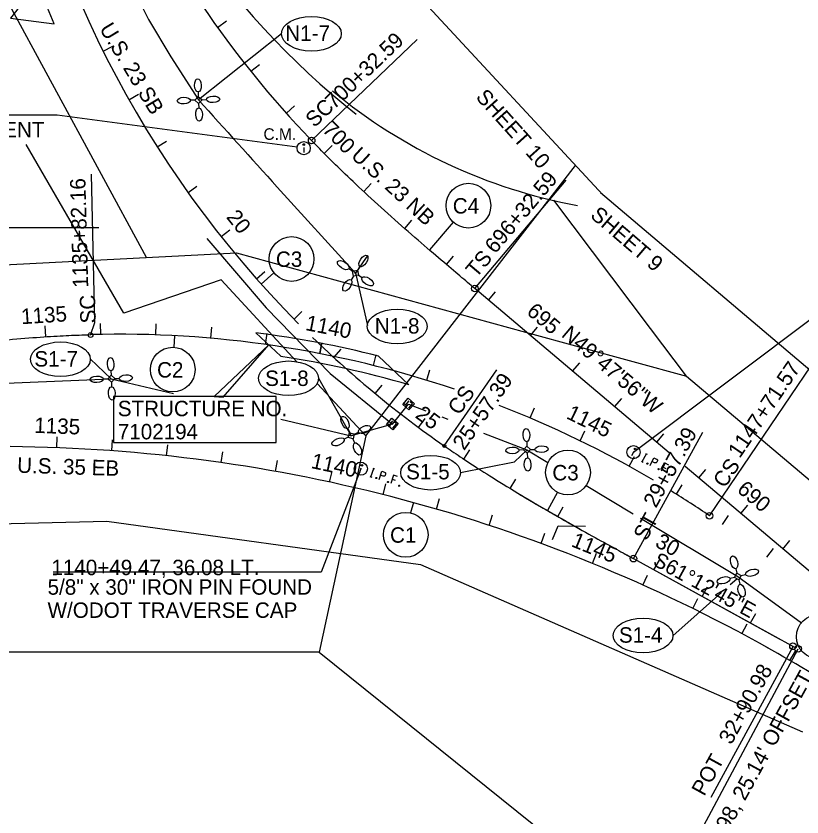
# Model space of a CAD drawing. Extents: x 310 to 1844719, y 48 to 494239.
# Drawn here: x 1837039 to 1838467, y 491132 to 492586 of the extents above; entities that cross this region are included whole.
import ezdxf

# ---------------------------------------------------------------- set-up
doc = ezdxf.new("R2010")
doc.units = 0
for name, color, linetype in [('BR_X_SV_Bottom_of_Beam_Text', 7, 'Continuous'), ('Default', 7, 'Continuous'), ('Guardrail', 7, 'Continuous'), ('LT_P_Control_Center', 7, 'Continuous'), ('LT_P_PullBox', 7, 'Continuous'), ('PV_X_Curb', 7, 'Continuous'), ('PV_X_EOP', 7, 'Continuous'), ('RW_X_CL_100_Stations', 7, 'Continuous'), ('RW_X_Esmt_LA', 7, 'Continuous'), ('SC_Scratch2', 7, 'Continuous'), ('Shoulder lines', 7, 'Continuous'), ('Traffic Sign', 7, 'Continuous'), ('UT_P_Electric_Cells', 7, 'Continuous'), ('VG_X_Tree_Line_Lt', 7, 'Continuous'), ('VG_X_Tree_Line_Rt', 7, 'Continuous')]:
    doc.layers.add(name, color=color, linetype=linetype)

msp = doc.modelspace()

# ---------------------------------------------------------------- linework, layer by layer
at = {"layer": 'BR_X_SV_Bottom_of_Beam_Text'}
for p, q in [((1837561.9, 492347.3), (1837561.9, 492338.5)), ((1838161.3, 491795.4), (1838157.3, 491787.5)), ((1837665.9, 491765.5), (1837663.1, 491757.1))]:
    msp.add_line(p, q, dxfattribs=at)
for points in [[(1838176.8, 491777.3), (1838184.1, 491791.5)], [(1838182.5, 491792.3), (1838185.7, 491790.7)], [(1838175.3, 491778), (1838178.4, 491776.5)], [(1838186.4, 491774.8), (1838186.9, 491774.6), (1838187, 491774.2), (1838187.1, 491773.6), (1838186.8, 491773), (1838186.3, 491772.7), (1838185.9, 491772.7), (1838185.4, 491772.9), (1838185.2, 491773.3), (1838185.2, 491773.9), (1838185.4, 491774.4), (1838186, 491774.7), (1838186.4, 491774.8)], [(1838190.8, 491770.2), (1838198, 491784.4), (1838202.8, 491782), (1838203.2, 491781.7), (1838203.8, 491781.1), (1838204, 491780.7), (1838204.1, 491780.4), (1838204.2, 491779.6), (1838204.3, 491778.9), (1838204, 491777.9), (1838203.3, 491776.5), (1838203, 491776.1), (1838202.4, 491775.6), (1838201.7, 491775), (1838201.1, 491774.8), (1838200.7, 491774.8), (1838200.1, 491774.8), (1838199.2, 491775.1), (1838194.5, 491777.5)], [(1837683.9, 491749.7), (1837689, 491764.9)], [(1837687.3, 491765.4), (1837690.7, 491764.3)], [(1838206.4, 491764.7), (1838206.9, 491764.4), (1838207.1, 491764), (1838207.2, 491763.4), (1838206.9, 491762.9), (1838206.4, 491762.6), (1838205.9, 491762.5), (1838205.5, 491762.7), (1838205.3, 491763.1), (1838205.2, 491763.7), (1838205.5, 491764.3), (1838206, 491764.6), (1838206.4, 491764.7)], [(1838224.9, 491770.8), (1838218.1, 491774.3), (1838210.9, 491760)], [(1838214.6, 491767.3), (1838219.4, 491764.9)], [(1837682.2, 491750.3), (1837685.5, 491749.1)], [(1837693.6, 491748.7), (1837694.1, 491748.5), (1837694.4, 491748.1), (1837694.5, 491747.5), (1837694.3, 491746.9), (1837693.9, 491746.6), (1837693.5, 491746.4), (1837692.9, 491746.6), (1837692.7, 491747), (1837692.6, 491747.6), (1837692.8, 491748.1), (1837693.2, 491748.5), (1837693.6, 491748.7)], [(1837698.7, 491744.7), (1837703.8, 491759.8), (1837708.8, 491758.1), (1837709.3, 491757.8), (1837710, 491757.3), (1837710.2, 491757), (1837710.4, 491756.7), (1837710.6, 491755.9), (1837710.7, 491755.2), (1837710.6, 491754.2), (1837710.1, 491752.8), (1837709.9, 491752.3), (1837709.4, 491751.7), (1837708.7, 491751), (1837708.2, 491750.8), (1837707.8, 491750.6), (1837707.2, 491750.6), (1837706.3, 491750.7), (1837701.3, 491752.4)], [(1837732.3, 491750.2), (1837725.1, 491752.6), (1837720, 491737.5)], [(1838225.6, 491754.9), (1838226.1, 491754.7), (1838226.3, 491754.3), (1838226.3, 491753.7), (1838226, 491753.1), (1838225.5, 491752.8), (1838225.1, 491752.8), (1838224.6, 491753), (1838224.4, 491753.4), (1838224.4, 491754), (1838224.7, 491754.6), (1838225.2, 491754.9), (1838225.6, 491754.9)], [(1837714.9, 491741.4), (1837715.4, 491741.3), (1837715.7, 491740.9), (1837715.8, 491740.3), (1837715.6, 491739.7), (1837715.1, 491739.4), (1837714.8, 491739.2), (1837714.2, 491739.4), (1837714, 491739.7), (1837713.8, 491740.3), (1837714, 491740.9), (1837714.5, 491741.3), (1837714.9, 491741.4)], [(1837722.6, 491745.2), (1837727.7, 491743.5)], [(1837735.3, 491734.5), (1837735.8, 491734.4), (1837736, 491734), (1837736.2, 491733.4), (1837736, 491732.8), (1837735.5, 491732.5), (1837735.1, 491732.3), (1837734.6, 491732.5), (1837734.4, 491732.8), (1837734.2, 491733.4), (1837734.4, 491734), (1837734.9, 491734.4), (1837735.3, 491734.5)]]:
    msp.add_lwpolyline(points, dxfattribs=at)
for centre, radius in [((1837561.9, 492346.2), 12), ((1837561.9, 492352.7), 1.6), ((1838160.8, 491794.4), 12), ((1838163.7, 491800.2), 1.6), ((1837665.5, 491764.4), 12), ((1837667.6, 491770.5), 1.6)]:
    msp.add_circle(centre, radius, dxfattribs=at)
at = {"layer": 'Default'}
for p, q in [((1838105.1, 492261.8), (1837503.3, 492910.5)), ((1837235, 492046.5), (1837058.1, 492352.7)), ((1837674.8, 491824.1), (1838055.3, 492314.6)), ((1838100.7, 492265.5), (1838804.8, 491669.7)), ((1837189.9, 492201.8), (1836753.1, 492201.8)), ((1837411.8, 492107.3), (1837235, 492046.5)), ((1837549.7, 491958.7), (1837411.8, 492107.3)), ((1838225.7, 491793), (1837872.5, 492091.5)), ((1837475, 492011.2), (1837520.5, 491968.4)), ((1837591.2, 491973.3), (1837595, 491993)), ((1837697.7, 491968.8), (1837753.1, 491916.6)), ((1837817.2, 491805.9), (1837912.9, 491943.6)), ((1837674.7, 491824), (1837586.3, 491919.2)), ((1837674.7, 491824), (1837590, 491431.3)), ((1838160.7, 491601.2), (1838286.7, 491830.6)), ((1838508.4, 491554.1), (1838254.8, 491768.4)), ((1838160.7, 491601.2), (1838453, 491440.6)), ((1838160.7, 491601.2), (1838425.3, 491455.8)), ((1838301.9, 491168.2), (1838450.8, 491441.8)), ((1837590, 491431.3), (1836154.6, 491431.3)), ((1837590, 491431.3), (1838683, 490553.9))]:
    msp.add_line(p, q, dxfattribs=at)
msp.add_circle((1837817.2, 491805.9), 2.69, dxfattribs=at)
for centre, radius, start, end in [((1838906.9, 493374.4), 1909.9, 189.0038, 224.841), ((1838954.8, 493681.9), 1909.9, 204.7226, 223.7988), ((1837226.4, 490098.6), 1909.9, 71.3891, 91.5249), ((1837226.4, 490098.6), 1928.7, 75.8578, 82.5942), ((1838906.9, 493374.4), 1909.9, 225.9055, 235.2124), ((1837226.4, 490098.6), 1892.7, 73.8425, 81.0615), ((1837226.4, 490098.6), 1909.9, 59.4577, 68.8036), ((1837004.6, 488939.8), 2864.8, 60.6408, 89.5206), ((1837226.4, 490098.6), 1909.9, 55.8426, 58.3012), ((1837004.6, 488939.8), 2864.8, 52.8425, 60.8195)]:
    msp.add_arc(centre, radius, start, end, dxfattribs=at)
for points, degree in [([(1837872.5, 492091.5), (1837864, 492098.7), (1837847, 492113), (1837813.1, 492141.8), (1837770.9, 492177.9), (1837720.7, 492221.8), (1837671.4, 492266.6), (1837631.1, 492304.8), (1837599.5, 492336.1), (1837584, 492352.1), (1837576.3, 492360.1)], 3), ([(1836777.7, 491969.3), (1836788.7, 491970.8), (1836810.7, 491973.7), (1836854.8, 491979.4), (1836909.9, 491986.4), (1836976.1, 491994), (1837042.5, 492000.4), (1837097.9, 492004.4), (1837142.3, 492006.7), (1837164.5, 492007.5), (1837175.6, 492007.8)], 3), ([(1837817.2, 491805.9), (1837826.3, 491799.5), (1837844.7, 491787), (1837881.8, 491762.6), (1837928.9, 491733), (1837986.2, 491698.9), (1838031.2, 491673.1), (1838057.2, 491658.5), (1838063.7, 491654.8)], 3), ([(1837817.2, 491805.9), (1837826.3, 491799.5), (1837844.7, 491787), (1837881.8, 491762.6), (1837928.9, 491733), (1837986.2, 491698.9), (1838044, 491665.8), (1838092.5, 491638.7), (1838131.5, 491617.3), (1838150.9, 491606.6), (1838160.7, 491601.2)], 3), ([(1838145.6, 491609.5), (1838150.7, 491606.7), (1838155.7, 491604), (1838160.7, 491601.2)], 2)]:
    msp.add_open_spline(points, degree=degree, dxfattribs=at)
at = {"layer": 'LT_P_Control_Center'}
for p, q in [((1837370.2, 492448.2), (1837370.5, 492440.1)), ((1837364.4, 492433.5), (1837356.3, 492433.1)), ((1837377.2, 492434), (1837385.3, 492434.3)), ((1837371.1, 492427.4), (1837371.4, 492419.3)), ((1837650.4, 492122.7), (1837643.7, 492127.2)), ((1837663.7, 492131.3), (1837659.3, 492124.6)), ((1837652.2, 492113.9), (1837647.8, 492107.2)), ((1837661.1, 492115.7), (1837667.8, 492111.3)), ((1837211.8, 491942.1), (1837212.1, 491934.1)), ((1837206, 491927.4), (1837197.9, 491927.1)), ((1837212.6, 491921.3), (1837213, 491913.2)), ((1837218.7, 491928), (1837226.8, 491928.3)), ((1837642.2, 491837.4), (1837645.6, 491830.1)), ((1837642.5, 491821.6), (1837635.2, 491818.2)), ((1837651, 491818.6), (1837654.4, 491811.2)), ((1837654.1, 491827.1), (1837661.4, 491830.5)), ((1837966.8, 491813.2), (1837967.2, 491805.1)), ((1837961.1, 491798.5), (1837953, 491798.1)), ((1837967.7, 491792.4), (1837968, 491784.3)), ((1837973.8, 491799), (1837981.9, 491799.4)), ((1838346.6, 491582.7), (1838348.6, 491574.9)), ((1838356.4, 491570.4), (1838364.3, 491572.5)), ((1838344.1, 491567.1), (1838336.3, 491565.1)), ((1838351.9, 491562.6), (1838354, 491554.8))]:
    msp.add_line(p, q, dxfattribs=at)
for points in [[(1837371.1, 492427.4), (1837364.4, 492433.5), (1837370.5, 492440.1), (1837377.2, 492434)], [(1837652.2, 492113.9), (1837650.4, 492122.7), (1837659.3, 492124.6), (1837661.1, 492115.7)], [(1837212.6, 491921.3), (1837206, 491927.4), (1837212.1, 491934.1), (1837218.7, 491928)], [(1837651.5, 491818.8), (1837642.8, 491820.9), (1837644.9, 491829.7), (1837653.7, 491827.6)], [(1837967.7, 491792.4), (1837961.1, 491798.5), (1837967.2, 491805.1), (1837973.8, 491799)], [(1838351.9, 491562.6), (1838344.1, 491567.1), (1838348.6, 491574.9), (1838356.4, 491570.4)]]:
    msp.add_lwpolyline(points, close=True, dxfattribs=at)
for centre, major_axis in [((1837369.7, 492460.2), (-0.5, 12)), ((1837344.3, 492432.6), (-12, -0.5)), ((1837397.3, 492434.8), (12, 0.5)), ((1837371.9, 492407.2), (-0.5, 12.1)), ((1837670.4, 492141.4), (6.6, 10.1)), ((1837633.6, 492133.9), (-10.1, 6.6)), ((1837677.9, 492104.6), (10.1, -6.6)), ((1837641.1, 492097.1), (6.7, 10.1)), ((1837211.3, 491954.2), (-0.5, 12)), ((1837238.9, 491928.8), (12, 0.5)), ((1837185.9, 491926.6), (-12, -0.5)), ((1837213.4, 491901.2), (-0.5, 12.1)), ((1837637, 491848.4), (-5.1, 10.9)), ((1837672.3, 491835.6), (10.9, 5.1)), ((1837966.3, 491825.3), (-0.5, 12)), ((1837624.3, 491813.1), (-10.9, -5.1)), ((1837659.6, 491800.3), (-5.1, 10.9)), ((1837940.9, 491797.6), (-12, -0.5)), ((1837993.9, 491799.9), (12, 0.5)), ((1837968.5, 491772.2), (-0.5, 12.1)), ((1838343.5, 491594.4), (-3.1, 11.7)), ((1838375.9, 491575.6), (11.7, 3.1)), ((1838324.6, 491562), (-11.7, -3.1)), ((1838357, 491543.1), (-3.1, 11.7))]:
    msp.add_ellipse(centre, major_axis=major_axis, ratio=0.5, dxfattribs=at)
at = {"layer": 'LT_P_PullBox'}
for p, q in [((1837232.9, 492674.8), (1837280, 492580)), ((1837280, 492580), (1837320.6, 492511.8)), ((1837320.6, 492511.8), (1837370.9, 492433.7)), ((1837513.8, 492275.6), (1837656.1, 492119.3)), ((1837385.9, 492182.1), (1837493.8, 492056.7)), ((1837493.8, 492056.7), (1837609.8, 491937.2)), ((1837609.8, 491937.2), (1837722.9, 491845.5)), ((1836774.6, 491909.1), (1837212.3, 491927.7)), ((1837212.3, 491927.7), (1837325.3, 491900.9)), ((1837520.6, 491854.6), (1837647.9, 491824.3)), ((1837813, 491858.3), (1837823.8, 491854.1)), ((1837722.9, 491845.5), (1837647.9, 491824.3)), ((1838074.8, 491734), (1838160.4, 491682.7))]:
    msp.add_line(p, q, dxfattribs=at)
for points in [[(1837090.5, 493031.9), (1837113.1, 492969.2), (1837145.8, 492884.3), (1837178.9, 492810.8), (1837187, 492786.1), (1837211.7, 492724.3), (1837232.9, 492674.8), (1837280, 492580), (1837320.6, 492511.8), (1837370.9, 492433.7)], [(1837722.9, 491845.5), (1837752.3, 491881.7), (1837783.9, 491869.5)], [(1837888.1, 491829.2), (1837967.2, 491798.7), (1838005.4, 491775.7)], [(1838173.7, 491674.7), (1838350.1, 491568.7), (1838465.7, 491484.9)]]:
    msp.add_lwpolyline(points, dxfattribs=at)
msp.add_arc((1887803.2, 537896.3), 67898.9, 222.033352, 222.213129, dxfattribs=at)
at = {"layer": 'PV_X_Curb'}
for p, q in [((1837276.3, 492148), (1837002.7, 492653)), ((1838015.7, 492251.9), (1838191.1, 492019.2)), ((1836800.5, 492123.5), (1837439.6, 492156.5)), ((1837439.6, 492156.5), (1837964.7, 492012.5)), ((1837964.7, 492012.5), (1838256.8, 491932.4)), ((1838191.1, 492019.2), (1838256.7, 491932.2)), ((1838256.8, 491932.4), (1839173.6, 491159.8)), ((1836167.8, 491643.5), (1837204.2, 491669.3)), ((1837204.2, 491669.3), (1837774.1, 491590.8)), ((1837774.1, 491590.8), (1838467.8, 491287.1))]:
    msp.add_line(p, q, dxfattribs=at)
for centre, radius, start, end in [((1838555, 493544.4), 1448.4, 195.5242, 231.7004), ((1838234.5, 493197.2), 970.9, 230.2756, 259.595)]:
    msp.add_arc(centre, radius, start, end, dxfattribs=at)
at = {"layer": 'PV_X_EOP'}
for p, q in [((1837405.3, 492565.4), (1837421.6, 492577.1)), ((1837197.5, 492522.5), (1837215.4, 492531.4)), ((1837465.9, 492485.8), (1837481.5, 492498.3)), ((1837244.5, 492434.2), (1837261.9, 492444)), ((1837530.5, 492409.5), (1837545.4, 492422.9)), ((1837295.9, 492348.5), (1837312.8, 492359.2)), ((1837599.1, 492336.7), (1837613.3, 492350.8)), ((1837351.8, 492265.6), (1837368.1, 492277.2)), ((1837671, 492267.3), (1837684.6, 492281.9)), ((1837745.3, 492200.3), (1837758.5, 492215.4)), ((1837412, 492185.7), (1837427.7, 492198.1)), ((1837821.1, 492135.1), (1837834, 492150.3)), ((1837476.3, 492109.1), (1837491.2, 492122.3)), ((1837897.4, 492070.5), (1837910.3, 492085.7)), ((1837544.4, 492036), (1837558.7, 492050)), ((1837093.6, 492004), (1837092.2, 492023.9)), ((1837193.5, 492008.2), (1837193.1, 492028.2)), ((1837293.4, 492007.3), (1837294.1, 492027.3)), ((1837393.2, 492001.2), (1837395, 492021.1)), ((1837492.6, 491989.9), (1837495.4, 492009.7)), ((1837973.8, 492005.9), (1837986.7, 492021.2)), ((1837616.4, 491966.5), (1837629.9, 491981.2)), ((1837688.8, 491951.7), (1837693.7, 491971.1)), ((1838050.1, 491941.4), (1838063.1, 491956.7)), ((1837785.2, 491924.9), (1837791, 491944.1)), ((1837691.8, 491900.9), (1837704.5, 491916.3)), ((1838126.5, 491876.8), (1838139.4, 491892.1)), ((1837973, 491856.5), (1837980.8, 491874.9)), ((1837770.6, 491839.3), (1837782.5, 491855.4)), ((1838064, 491815), (1838072.7, 491833)), ((1837113.6, 491802.5), (1837114.3, 491822.5)), ((1838202.9, 491812.3), (1838215.8, 491827.6)), ((1837213.4, 491797), (1837214.9, 491816.9)), ((1837313, 491787.9), (1837315.2, 491807.8)), ((1837412.2, 491775.4), (1837415.1, 491795.2)), ((1837852.5, 491781.9), (1837863.5, 491798.6)), ((1837510.9, 491759.5), (1837514.5, 491779.2)), ((1838152.7, 491768.9), (1838162.4, 491786.4)), ((1838279.3, 491747.7), (1838292.2, 491763)), ((1837609, 491740.1), (1837613.3, 491759.6)), ((1837706.4, 491717.3), (1837711.3, 491736.7)), ((1837936.9, 491728.4), (1837947.3, 491745.5)), ((1838238.8, 491718.1), (1838249.4, 491735.1)), ((1837802.9, 491691.1), (1837808.5, 491710.3)), ((1838023.2, 491677.8), (1838033.1, 491695.2)), ((1838355.7, 491683.2), (1838368.6, 491698.5)), ((1837898.4, 491661.6), (1837904.7, 491680.6)), ((1838322.2, 491662.9), (1838333.6, 491679.3)), ((1837992.9, 491628.7), (1837999.8, 491647.5)), ((1838432, 491618.6), (1838444.9, 491633.9)), ((1838402.8, 491603.8), (1838415, 491619.7)), ((1838086.1, 491592.6), (1838093.7, 491611.1)), ((1838198, 491580.7), (1838207.7, 491598.2)), ((1838178, 491553.2), (1838186.2, 491571.5)), ((1838285.7, 491532.5), (1838295.3, 491550.1)), ((1838268.5, 491510.7), (1838277.4, 491528.6)), ((1838373.3, 491484.4), (1838382.9, 491501.9)), ((1838357.5, 491465), (1838366.9, 491482.6)), ((1838444.8, 491416.2), (1838454.8, 491433.5))]:
    msp.add_line(p, q, dxfattribs=at)
at = {"layer": 'RW_X_CL_100_Stations'}
for p, q in [((1837507.9, 492120), (1837484.9, 492099.4)), ((1838459.5, 491437), (1837875.9, 490345.5))]:
    msp.add_line(p, q, dxfattribs=at)
msp.add_circle((1837539.8, 492145.1), 40.6, dxfattribs=at)
at = {"layer": 'RW_X_Esmt_LA'}
for p, q in [((1838013.8, 491635.9), (1838023.9, 491660.5)), ((1838023.9, 491660.5), (1838073.9, 491660.4))]:
    msp.add_line(p, q, dxfattribs=at)
at = {"layer": 'SC_Scratch2'}
msp.add_lwpolyline([(1837108.7, 492572.1), (1837078.7, 492644.9), (1837029.6, 492582.1)], close=True, dxfattribs=at)
at = {"layer": 'Shoulder lines'}
for p, q in [((1837521.5, 492553.9), (1837370.9, 492433.7)), ((1837114.2, 492406.3), (1836652.1, 492406.6)), ((1837550, 492347.8), (1837114.2, 492406.3)), ((1837676.4, 492149.4), (1837654.6, 492117.5)), ((1837655.7, 492119.7), (1837677.5, 492024.5)), ((1838160.8, 491794.4), (1838550.1, 492087.1)), ((1837174.4, 491964), (1837212.4, 491927.7)), ((1837588.7, 491928.5), (1837647.9, 491824.3)), ((1837665.5, 491764.4), (1837593.4, 491576.4)), ((1837593.4, 491576.4), (1837107.2, 491576.4)), ((1838336.4, 491554.2), (1838348.2, 491564.8)), ((1838232.3, 491461.2), (1838320.5, 491540))]:
    msp.add_line(p, q, dxfattribs=at)
msp.add_lwpolyline([(1837846.8, 491757.3), (1837944.4, 491777.2), (1837967.4, 491798.8)], dxfattribs=at)
for centre in [(1837575.8, 492553.9), (1837731.8, 492022.7), (1837120, 491963), (1837534.4, 491928.5), (1837792.4, 491757.2), (1838178.1, 491461.6)]:
    msp.add_ellipse(centre, major_axis=(-54.4, 0), ratio=0.57803, dxfattribs=at)
at = {"layer": 'Traffic Sign'}
for p, q in [((1837576.3, 492360.1), (1837767.7, 492543.6)), ((1837872.5, 492091.5), (1838038.7, 492288.2)), ((1837833.4, 492212.2), (1837790.3, 492161.4)), ((1837327.3, 492005.8), (1837326.2, 491984.9)), ((1838298.8, 491679), (1838483.3, 491951.1)), ((1838022.6, 491721.8), (1838004.6, 491688.4)), ((1837761.3, 491703), (1837756.1, 491684.1))]:
    msp.add_line(p, q, dxfattribs=at)
msp.add_lwpolyline([(1837174.8, 492007), (1837182.5, 492029.7), (1837176.5, 492299.1)], dxfattribs=at)
for centre, radius in [((1837576.3, 492360.1), 6), ((1837861, 492241.9), 40.6), ((1837872.5, 492091.5), 6), ((1837174.8, 492007), 4.36), ((1837324.1, 491944.3), 40.6), ((1838041.8, 491757.6), 40.6), ((1837747.1, 491644.5), 40.6), ((1838298.8, 491679), 6), ((1838160.7, 491601.2), 6), ((1838497.4, 491459.5), 40.6), ((1838450.4, 491442.1), 6), ((1838459.7, 491437.4), 6)]:
    msp.add_circle(centre, radius, dxfattribs=at)
at = {"layer": 'UT_P_Electric_Cells'}
for p, q in [((1837752.3, 491881.7), (1837752.3, 491881.7)), ((1837722.9, 491845.5), (1837722.9, 491845.5))]:
    msp.add_line(p, q, dxfattribs=at)
for points in [[(1837752.9, 491871.2), (1837741.7, 491881), (1837751.6, 491892.3), (1837762.8, 491882.4)], [(1837723.6, 491834.9), (1837712.3, 491844.8), (1837722.2, 491856.1), (1837733.5, 491846.2)]]:
    msp.add_lwpolyline(points, close=True, dxfattribs=at)
for points in [[(1837749.1, 491877.8), (1837744.5, 491881.9)], [(1837746.8, 491879.9), (1837753.4, 491887.4)], [(1837753, 491874.4), (1837759.6, 491881.9), (1837755.5, 491885.5)], [(1837717.4, 491843.7), (1837724, 491851.2)], [(1837723.7, 491838.2), (1837730.3, 491845.7), (1837726.2, 491849.3)], [(1837719.8, 491841.6), (1837715.1, 491845.7)]]:
    msp.add_lwpolyline(points, dxfattribs=at)
at = {"layer": 'VG_X_Tree_Line_Lt'}
for p, q in [((1837498.6, 491989), (1837399.2, 491895.2)), ((1837415.9, 491894.4), (1837498.6, 491989)), ((1837399.2, 491895.2), (1837415.9, 491894.4))]:
    msp.add_line(p, q, dxfattribs=at)
msp.add_lwpolyline([(1837511.9, 491895.2), (1837216.2, 491895.2), (1837216.2, 491811.8), (1837511.9, 491811.8)], close=True, dxfattribs=at)
at = {"layer": 'VG_X_Tree_Line_Rt'}
msp.add_line((1837595, 491993), (1837591.2, 491973.3), dxfattribs=at)

# ---------------------------------------------------------------- texts
at = {"layer": 'BR_X_SV_Bottom_of_Beam_Text'}
msp.add_text('C.M.', height=21, dxfattribs=at).set_placement((1837488.8, 492361.3))
at = {"layer": 'Default'}
for s, rotation, p in [('25+57.39', 55.2124, (1837853.2, 491796.2)), ('CS', 55.2124, (1837844.4, 491860)), ('29+57.39', 61.2124, (1838201.6, 491691.7)), ('ST', 61.2124, (1838183.7, 491631.6)), ('32+90.98', 61.2124, (1838338.5, 491262.1)), ('POT', 61.2124, (1838289.2, 491168.7))]:
    msp.add_text(s, height=28, rotation=rotation, dxfattribs=at).set_placement(p)
for s, p in [('STRUCTURE NO.', (1837224.3, 491859.7)), ('7102194', (1837224.3, 491817.7))]:
    msp.add_text(s, height=28, dxfattribs=at).set_placement(p)
at = {"layer": 'Guardrail'}
for s, height, rotation, p in [('N49°47\'56"W', 28, 319.7988, (1838028.2, 492005.4)), ('S61°12\'45"E', 27.104, 331.2124, (1838194.2, 491590.4))]:
    msp.add_text(s, height=height, rotation=rotation, dxfattribs=at).set_placement(p)
at = {"layer": 'PV_X_EOP'}
for s, rotation, p in [('CONCRETE MONUMENT ', 0.0079, (1836650.2, 492365.9)), ('700', 314.7367, (1837594.1, 492378)), ('20', 308.4908, (1837420.2, 492220.7)), ('695', 319.7988, (1837965, 492046.6)), ('25', 323.4908, (1837762.7, 491858.5)), ('1135', 357.8196, (1837072.2, 491829.6)), ('1140', 347.8196, (1837573.8, 491765.9)), ('690', 319.7988, (1838347, 491723.8)), ('1145', 337.8195, (1838046.1, 491624.1)), ('30', 331.2124, (1838198.2, 491624.2)), ('1140+49.47, 36.08 LT.', 0.0079, (1837103.7, 491571.2)), ('5/8" x 30" IRON PIN FOUND ', 0.0079, (1837096.8, 491535.7)), ('W/ODOT TRAVERSE CAP', 0.0079, (1837096.8, 491493.7))]:
    msp.add_text(s, height=28, rotation=rotation, dxfattribs=at).set_placement(p)
at = {"layer": 'RW_X_CL_100_Stations'}
msp.add_text("U.S. 23 SB STA. 32+90.98 = U.S. 35 EB STA. 32+90.98, 25.14' OFFSET ", height=28, rotation=61.2354, dxfattribs=at).set_placement((1837902.8, 490321.8))
at = {"layer": 'Shoulder lines'}
for s, rotation, p in [('U.S. 23 SB', 301.0141, (1837190.1, 492563.2)), ('SHEET 10', 311.8708, (1837872.9, 492438)), ('U.S. 23 NB', 317.4244, (1837646.1, 492330.3)), ('SHEET 9', 319.4615, (1838080.6, 492221.7)), ('U.S. 35 EB', 358.1606, (1837041.2, 491757.2))]:
    msp.add_text(s, height=28, rotation=rotation, dxfattribs=at).set_placement(p)
for s, p in [('N1-7', (1837528.4, 492540.9)), ('C3', (1837511.4, 492130.7)), ('N1-8', (1837691, 492009.7)), ('S1-7', (1837072.8, 491949.8)), ('S1-8', (1837491.8, 491914.6)), ('S1-5', (1837747.9, 491745.1)), ('S1-4', (1838134.3, 491448.6))]:
    msp.add_text(s, height=28, dxfattribs=at).set_placement(p)
at = {"layer": 'Traffic Sign'}
for s, rotation, p in [('700+32.59', 43.7988, (1837617.2, 492415.5)), ('SC', 43.7988, (1837581.4, 492382.4)), ('696+32.59', 49.7988, (1837909.6, 492153.2)), ('1135+82.16', 91.5249, (1837170.7, 492093.3)), ('TS', 49.7988, (1837875.1, 492109.4)), ('SC', 91.5249, (1837184.4, 492028.5)), ('1135', 3.7366, (1837049.6, 492026.6)), ('1140', 348.9897, (1837563.7, 492016.2)), ('1147+71.57', 55.8426, (1838353.6, 491782)), ('1145', 333.9897, (1838037.1, 491856.5)), ('CS', 55.8426, (1838326.4, 491727.7))]:
    msp.add_text(s, height=28, rotation=rotation, dxfattribs=at).set_placement(p)
for s, p in [('C4', (1837832.6, 492227.5)), ('C2', (1837295.6, 491929.9)), ('C3', (1838013.4, 491743.2)), ('C1', (1837718.7, 491630.1))]:
    msp.add_text(s, height=28, dxfattribs=at).set_placement(p)

doc.saveas('drawing.dxf')
